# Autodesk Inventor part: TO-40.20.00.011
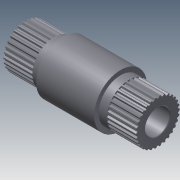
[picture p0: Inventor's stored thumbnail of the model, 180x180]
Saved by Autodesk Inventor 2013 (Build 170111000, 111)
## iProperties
Created: 2012-02
Part Number: TO-40.20.00.011
Material: Steel, Mild
Document SubType Name: Modeling
Designer: tedescj
Mass: 8156.12 g
Surface Area: 1203.33 cm^2
Volume: 1037.67 cm^3
Density: 7.86 g/cm^3
Author: tedescj
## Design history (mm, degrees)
sketch "Sketch1"
  geometry: C1 r 40 at (-44.134, 0) reference; 2 further points
  constraints: 1 centre point, 3 other
extrude "Extrusion1" new body sketch "Sketch1" stored distance "d0" = 242; taper "d1" = 0 deg
sketch "Sketch2"
  geometry: C1 r 48.268 at (-44.134, 0) reference; 1 further point
  constraints: 1 centre point, 2 other
extrude "Extrusion2" join sketch "Sketch2" stored distance "d2" = 106; taper "d3" = 0 deg
feature "Base1"
feature "Base2"
combine "Combine1"
  body "Solid2"
combine "Combine2"
  body "Solid3"
hole "Hole1" diameter "d6" = 45; stored, may be unused: countersink angle "d10" = 90 deg, drill point angle "d12" = 118 deg; dims "d4" = 10, "d5" = 10, "d7" = 6, "d8" = 4, "d9" = 2, "d11" = 8
chamfer "Chamfer1" distance "d13" = 1; stored, may be unused: second distance "d14" = 2, angle "d15" = 45 deg
body "Solid1"
